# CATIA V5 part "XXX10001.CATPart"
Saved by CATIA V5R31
Part number: XXX10001
Bounding box of the stored display mesh (mm): x -703.934 to -618.881, y -100.603 to -4, z -13.407 to 43.456
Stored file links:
  \\cad-nas02\CATIA1212\BODY_DEPARTMENT8\JAMA\変換データ\STEP3_最終_20240115\01_いすゞ板金\new_ファイル名修正後\CATIA_V5_20240122\XXX10001.CATPart
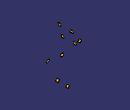
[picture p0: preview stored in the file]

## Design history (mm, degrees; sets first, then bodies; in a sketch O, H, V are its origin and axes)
Set1 "Spot"
  Set2 "79334x79283!4"
    Set3 "SpotPoint.1"
      Point1 "Position.1": stored without definition
      DatumCurve1 "SpotSymbol.1"
    Set4 "SpotPoint.2"
      Point2 "Position.2": stored without definition
      DatumCurve2 "SpotSymbol.2"
  Set5 "79283x29655!4"
    Set6 "SpotPoint.1"
      Point3 "Position.1": stored without definition
      DatumCurve3 "SpotSymbol.1"
  Set7 "79265x79283!4"
    Set8 "SpotPoint.1"
      Point4 "Position.1": stored without definition
      DatumCurve4 "SpotSymbol.1"
    Set9 "SpotPoint.2"
      Point5 "Position.2": stored without definition
      DatumCurve5 "SpotSymbol.2"
  Set10 "31819x79265!4"
    Set11 "SpotPoint.1"
      Point6 "Position.1": stored without definition
      DatumCurve6 "SpotSymbol.1"
    Set12 "SpotPoint.2"
      Point7 "Position.2": stored without definition
      DatumCurve7 "SpotSymbol.2"
    Set13 "SpotPoint.3"
      Point8 "Position.3": stored without definition
      DatumCurve8 "SpotSymbol.3"
    Set14 "SpotPoint.4"
      Point9 "Position.4": stored without definition
      DatumCurve9 "SpotSymbol.4"
Body1 (main body)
